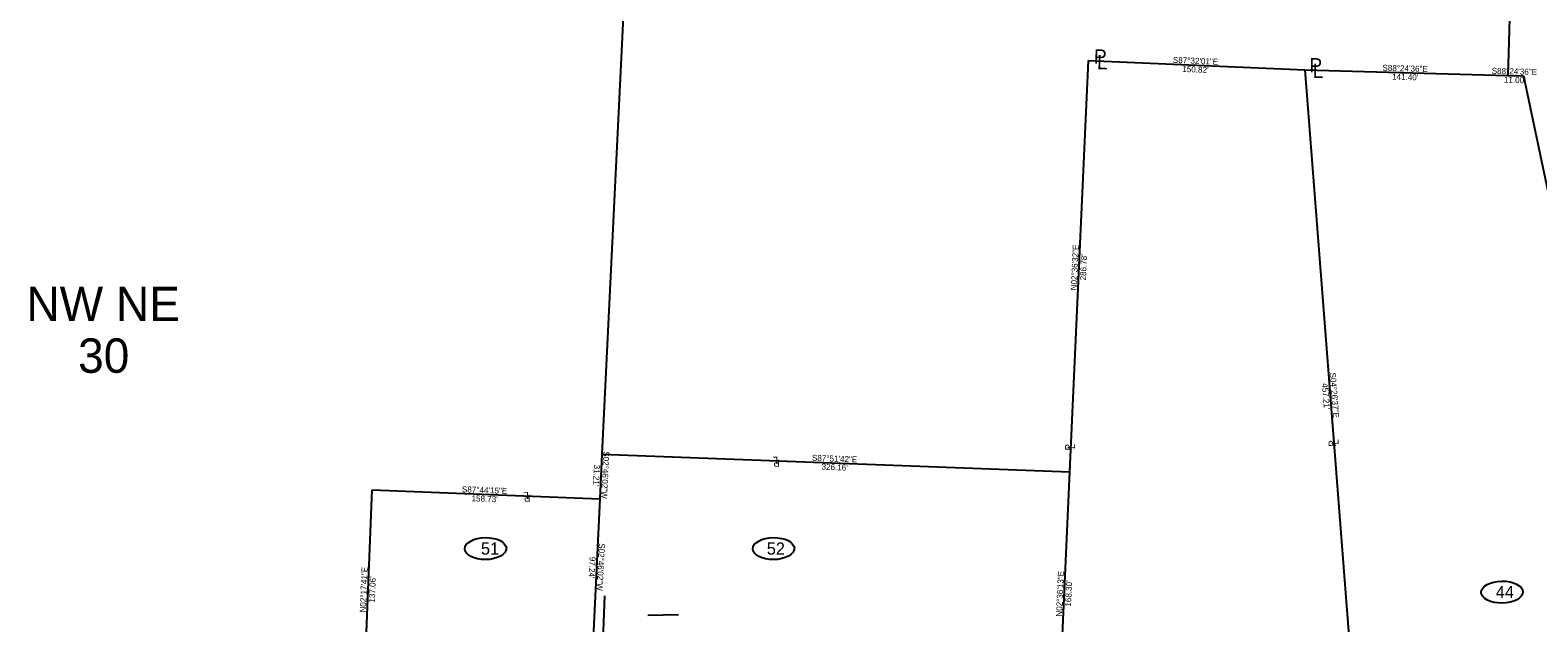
# Model space of a CAD drawing. Extents: x 1145508 to 2262867, y -3126236 to 2021677.
# Drawn here: x 1149992 to 1151042, y 2020265 to 2020678 of the extents above; entities that cross this region are included whole.
import ezdxf

# ---------------------------------------------------------------- set-up
doc = ezdxf.new("R2010")
doc.units = 0
for name, color, linetype in [('DSN_RDWY_Alignment', 7, 'Continuous'), ('DSN_ROW_Annotation', 7, 'Continuous'), ('DSN_ROW_Line-Annotation', 7, 'Continuous'), ('DSN_ROW_Prop-Line', 7, 'Continuous'), ('DSN_ROW_Prop-Line-Annotation', 7, 'Continuous'), ('EX_QSECTION', 7, 'Continuous'), ('EX_ROW_ANNOT', 7, 'Continuous'), ('EX_SIGN', 7, 'Continuous'), ('SHET_Annotations', 7, 'Continuous')]:
    doc.layers.add(name, color=color, linetype=linetype)

msp = doc.modelspace()

# ---------------------------------------------------------------- linework, layer by layer
at = {"layer": 'DSN_RDWY_Alignment'}
msp.add_line((1150384.5, 2020092.6), (1150392.4, 2020284), dxfattribs=at)
at = {"layer": 'DSN_ROW_Line-Annotation'}
for centre in [(1150309.2, 2020316.8), (1150509.8, 2020316.8), (1151017.2, 2020286.5)]:
    msp.add_ellipse(centre, major_axis=(14.5, 0.2), ratio=0.529773, dxfattribs=at)
at = {"layer": 'DSN_ROW_Prop-Line'}
for p, q in [((1151025.4, 2020796.4), (1151021.3, 2020646.5)), ((1150716.2, 2020370.4), (1150729.2, 2020656.9)), ((1150729.2, 2020656.9), (1150879.9, 2020650.4)), ((1150879.9, 2020650.4), (1150915.3, 2020194.6)), ((1150879.9, 2020650.4), (1151021.3, 2020646.5)), ((1151021.3, 2020646.5), (1151032.3, 2020646.2)), ((1151032.3, 2020646.2), (1151083.9, 2020400.1)), ((1150390.3, 2020382.6), (1150716.2, 2020370.4)), ((1150708.5, 2020202.3), (1150716.2, 2020370.4)), ((1150224.7, 2020220.7), (1150230.2, 2020357.7)), ((1150230.2, 2020357.7), (1150388.8, 2020351.4))]:
    msp.add_line(p, q, dxfattribs=at)
at = {"layer": 'EX_QSECTION'}
for p, q in [((1150446.1, 2021536.9), (1150390.3, 2020382.6)), ((1150390.3, 2020382.6), (1150388.8, 2020351.4)), ((1150388.8, 2020351.4), (1150384.1, 2020254.3))]:
    msp.add_line(p, q, dxfattribs=at)
at = {"layer": 'EX_SIGN'}
msp.add_line((1150422.3, 2020270.5), (1150443.6, 2020270.8), dxfattribs=at)

# ---------------------------------------------------------------- texts
at = {"layer": 'DSN_ROW_Annotation'}
for s, rotation, p in [('S87°32\'01"E', 357.5336, (1150787.9, 2020655.3)), ("150.82'", 357.5336, (1150794.5, 2020649)), ('S88°24\'36"E', 358.4101, (1150933.9, 2020649.8)), ('S88°24\'36"E', 358.4101, (1151010, 2020647.7)), ("141.40'", 358.4101, (1150940.6, 2020643.6)), ("11.00'", 358.4101, (1151018.5, 2020641.5)), ('N02°36\'32"E', 87.391, (1150721, 2020496.7)), ("286.78'", 87.391, (1150727.4, 2020503.6)), ('S04°26\'37"E', 274.4437, (1150897.2, 2020439.3)), ("457.21'", 274.4437, (1150891.8, 2020431.9)), ('S87°51\'42"E', 357.8615, (1150536.5, 2020378)), ("326.16'", 357.8615, (1150543.2, 2020371.8)), ('S87°44\'15"E', 357.7374, (1150292.7, 2020356.1)), ("158.73'", 357.7374, (1150299.4, 2020349.8)), ('N02°17\'41"E', 87.7053, (1150225.8, 2020272.2)), ("137.06'", 87.7053, (1150232.1, 2020279.1)), ('N02°36\'13"E', 87.3964, (1150710.7, 2020269.3)), ("168.30'", 87.3964, (1150717, 2020276.3))]:
    msp.add_text(s, height=4.2, rotation=rotation, dxfattribs=at).set_placement(p)
at = {"layer": 'DSN_ROW_Line-Annotation'}
for s, p in [('51', (1150306, 2020312.6)), ('52', (1150505.1, 2020312.6)), ('44', (1151012.9, 2020282.3))]:
    msp.add_text(s, height=8.5, dxfattribs=at).set_placement(p)
at = {"layer": 'DSN_ROW_Prop-Line-Annotation'}
for s, height, rotation, p in [('P', 10, 358.4691, (1150732.8, 2020654.8)), ('L', 10, 358.4691, (1150735, 2020650.9)), ('P', 10, 359.7974, (1150883, 2020648.6)), ('L', 10, 359.7974, (1150885.3, 2020644.8)), ('P', 5, 87.5589, (1150717.8, 2020385.1)), ('L', 5, 87.5589, (1150719.7, 2020386.2)), ('P', 5, 93.7882, (1150901.6, 2020388.1)), ('L', 5, 93.7882, (1150903.5, 2020389.4)), ('L', 5, 179.0826, (1150513, 2020380.8)), ('P', 5, 179.0826, (1150514.2, 2020378.8)), ('L', 5, 179.0826, (1150339.3, 2020356.3)), ('P', 5, 179.0826, (1150340.5, 2020354.4))]:
    msp.add_text(s, height=height, rotation=rotation, dxfattribs=at).set_placement(p)
at = {"layer": 'EX_ROW_ANNOT'}
for s, p in [("31.21'", (1150384.8, 2020375.4)), ("31.21'", (1150384.8, 2020375.4)), ('S02°46\'02"W', (1150391.3, 2020384.7)), ('S02°46\'02"W', (1150391.3, 2020384.7)), ('S02°46\'02"W', (1150388.2, 2020320.6)), ('S02°46\'02"W', (1150388.2, 2020320.6)), ("97.24'", (1150381.7, 2020311.2)), ("97.24'", (1150381.7, 2020311.2))]:
    msp.add_text(s, height=4.2, rotation=267.2328, dxfattribs=at).set_placement(p)
at = {"layer": 'SHET_Annotations'}
for s, p in [('NW NE', (1149989.4, 2020475.3)), ('30', (1150025.4, 2020439.3))]:
    msp.add_text(s, height=24, dxfattribs=at).set_placement(p)

doc.saveas('drawing.dxf')
